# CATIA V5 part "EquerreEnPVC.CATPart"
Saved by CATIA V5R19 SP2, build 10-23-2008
Part number: PlaqueMesureAngle
Bounding box of the stored display mesh (mm): x 0 to 55, y -25 to 25, z -25 to 25
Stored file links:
  D:\SCHOOL\FRANCE\BANC_POUTRE_EN_MOUSSE\EquerreEnPVC.CATPart
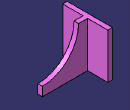
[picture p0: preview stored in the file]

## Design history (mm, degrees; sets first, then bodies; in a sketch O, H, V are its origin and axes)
AxisSystem1: origin (0, 0, 0), X (1, 0, 0), Y (0, 1, 0), Z (0, 0, 1)
Body1 (main body)
  Sketch1 on yz-plane, origin (0, 0, 0), H (0, 1, 0), V (0, 0, 1)
    line L1 (25, 25) -> (25, -25)
    line L2 (25, -25) -> (-25, -25)
    line L3 (-25, -25) -> (-25, 25)
    line L4 (-25, 25) -> (25, 25)
    length L4 = 50
    length L1 = 50
    vertical: L1 V, L3 V
    horizontal: L2 H, L4 H
    equidistance: L1 L3 O, L2 L4 O
  Pad1: profile Sketch1, direction (1, 0, 0), length 5
  Sketch2 on ZX plane of AxisSystem1, origin (0, 0, 0), H (0, 0, 1), V (1, 0, 0)
    point P1 (0, 30)
    line L1 (25, 55) -> (25, 5)
    line L2 (25, 5) -> (-25, 5)
    line L3 (-25, 5) -> (-25, 55)
    line L4 (-25, 55) -> (25, 55)
    reference projected line E1 (-50, 5) -> (50, 5) from edge [face of Pad1 from Sketch1.L1 | end face of Pad1]
    reference projected line E2 (-25, 0) -> (-25, 10) from edge [face of Pad1 from Sketch1.L1 | face of Pad1 from Sketch1.L2]
    distance H P1 = 30
    coincidence: P1 V, L2 E1, L3 E2
    vertical: L1 V, L3 V
    horizontal: L2 H, L4 H
    equidistance: L1 L3 P1, L2 L4 P1
  Pad2: profile Sketch2, direction (0, 1, 0), length 2.5, opposite side length 2.5
  Sketch3 on end face of Pad2, origin (0, 2.5, 0), H (-1, 0, 0), V (0, 0, 1)
    point P1 (-55, 25)
    reference projected line E1 (-10, 25) -> (-110, 25) from edge [face of Pad2 | end face of Pad2]
    reference projected line E2 (-55, 50) -> (-55, -50) from edge [face of Pad2 from Sketch2.L4 | end face of Pad2]
    arc A1 centre (-55, 25) radius 40 from (-55, -15) to (-15, 25) ccw
    point P2 (-55, -15)
    point P3 (-15, 25)
    reference projected line E3 (-10, 25) -> (-110, 25) from edge [face of Pad2 | end face of Pad2]
    reference projected line E4 (-55, 50) -> (-55, -50) from edge [face of Pad2 from Sketch2.L4 | end face of Pad2]
    radius A1 = 40
    coincidence: E1 P1, P1 E2, P3 E3, P2 E4
  Pocket1: profile Sketch3, direction (0, -1, 0), through (limit type 6)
